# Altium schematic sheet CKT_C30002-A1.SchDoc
size 330 x 219 mm; PageSetup: Record=PageOptions|CenterHorizontal=True|CenterVertical=True|PrintScale=0.89|XCorrection=1.00|YCorrection=1.00|PrintKind=0|BorderSize=5000000|LeftOffset=0|BottomOffset=0|Orientation=2|PaperLength=1000|PaperWidth=1000|Scale=100|PaperSource=7|PrintQuality=-4|MediaType=1|DitherType=10|PaperKind=A4|PrintScaleMode=1
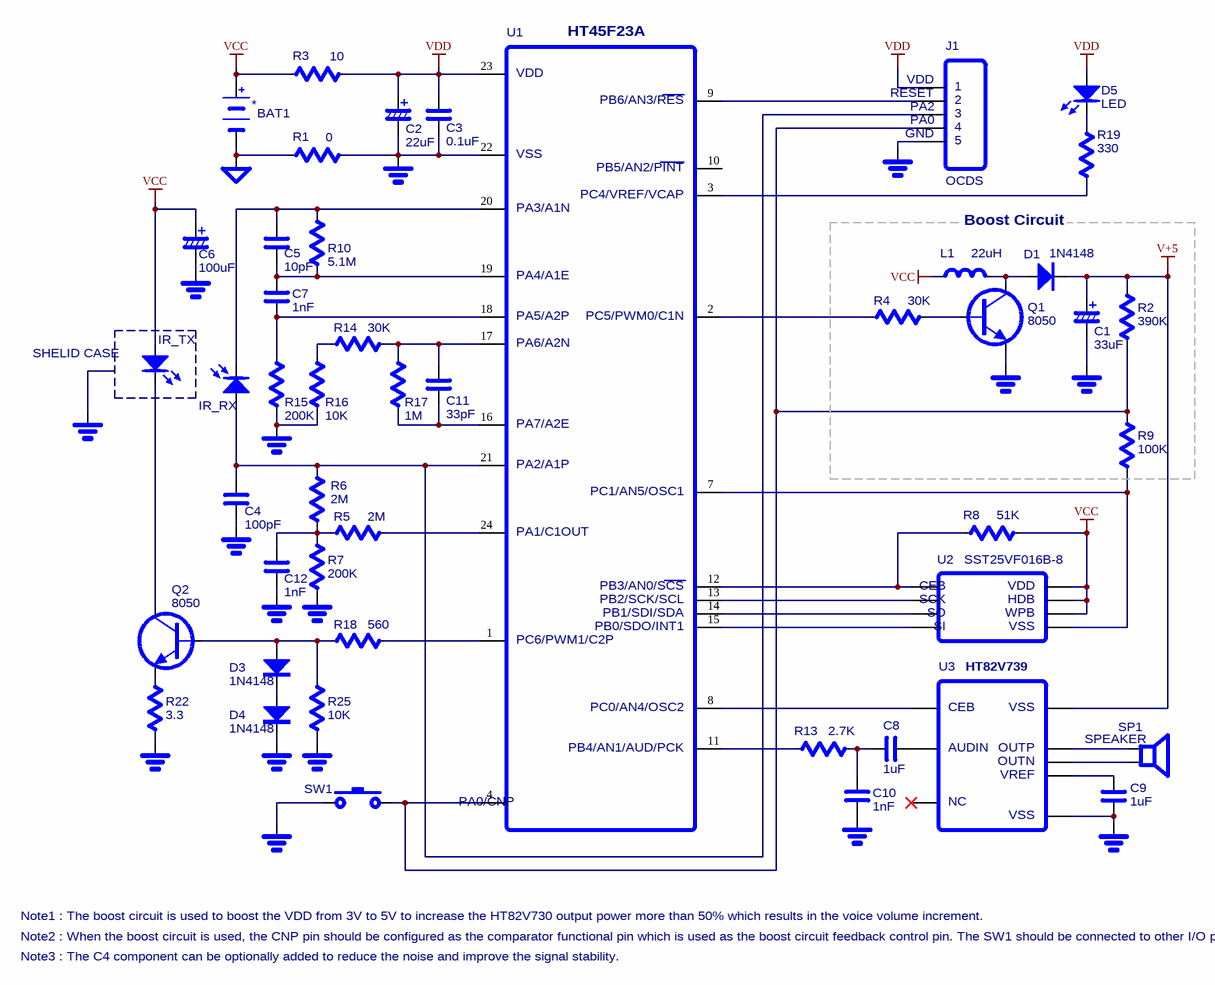
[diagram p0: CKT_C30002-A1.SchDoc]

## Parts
(Parts that share a designator on the sheet are numbered #1, #2 ... from top to bottom, then left to right.)
*18#1  GND(1)  (value not drawn)
*18#2  GND(1)  (value not drawn)
*18#3  GND(1)  (value not drawn)
*18#4  GND(1)  (value not drawn)
*18#5  GND(1)  (value not drawn)
*18#6  GND(1)  (value not drawn)
*18#7  GND(1)  (value not drawn)
*18#8  GND(1)  (value not drawn)
*18#9  GND(1)  (value not drawn)
*18#10  GND(1)  (value not drawn)
*18#11  GND(1)  (value not drawn)
*18#12  GND(1)  (value not drawn)
*18#13  GND(1)  (value not drawn)
*18#14  GND(1)  (value not drawn)
*18#15  GND(1)  (value not drawn)
*18#16  GND(1)  (value not drawn)
BAT1  *  [CR2032]
C1  33uF
C2  22uF
C3  0.1uF
C4  100pF
C5  10pF
C6  100uF
C7  1nF
C8  1uF
C9  1uF
C10  1nF
C11  33pF
C12  1nF
D1  1N4148  [SMC]
D3  1N4148  [SMC]
D4  1N4148  [SMC]
D5  LED  [LED3M]
D?  IR_RX  [LED3M]
f6  GND(2)  (value not drawn)
J1  OCDS
L1  22uH
LED?  IR_TX  [LED3M]
Q1  8050  [TO-226-AA]
Q2  8050  [TO-226-AA]
R1  0
R2  390K
R3  10
R4  30K
R5  2M
R6  2M
R7  200K
R8  51K
R9  100K
R10  5.1M
R13  2.7K
R14  30K
R15  200K
R16  10K
R17  1M
R18  560
R19  330
R22  3.3
R25  10K
SP1  SPEAKER  [PIN2]
SW1  SW(2)  (value not drawn)
U1  HT45F23A  [HT45F23A_24SSOP]
U2  SST25VF016B-8  [H8]
U3  HT82V739

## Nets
V+5: C1.1 D1.2(K) R2.2 U3.8(VDD)
VCC: BAT1.1(+) C6.1 L1.1 LED?.1(A) R3.1 R8.1 U2.3(WPB) U2.7(HDB) U2.8(VDD)
VDD: C2.1 C3.2 D5.1(A) J1.1(VDD) R3.2 U1.23(VDD)
Net*18#1_?1: *18#1.?1 J1.5(GND)
Net*18#2_?1: *18#2.?1 C2.2 C3.1 R1.2 U1.22(VSS)
Net*18#3_?1: *18#3.?1 C6.2
Net*18#4_?1: *18#4.?1 Q1.3(E)
Net*18#5_?1: *18#5.?1 C1.2
Net*18#7_?1: *18#7.?1 R15.1 R16.1
Net*18#8_?1: *18#8.?1 C4.2
Net*18#9_?1: *18#9.?1 C12.1
Net*18#10_?1: *18#10.?1 R7.1
Net*18#11_?1: *18#11.?1 R22.1
Net*18#12_?1: *18#12.?1 D4.2(K)
Net*18#13_?1: *18#13.?1 R25.1
Net*18#14_?1: *18#14.?1 C10.2
Net*18#15_?1: *18#15.?1 SW1.1
Net*18#16_?1: *18#16.?1 C9.1 U3.4(VSS)
NetBAT1_2: BAT1.2(-) f6.?1 R1.1
NetC4_1: C4.1 D?.1(A) J1.3(PA2) R6.2 U1.21(PA2/A1P)
NetC5_1: C5.1 C7.2 R10.1 U1.19(PA4/A1E)
NetC5_2: C5.2 D?.2(K) R10.2 U1.20(PA3/A1N)
NetC7_1: C7.1 R15.2 U1.18(PA5/A2P)
NetC8_1: C8.1 U3.2(AUDIN)
NetC8_2: C8.2 C10.1 R13.1
NetC9_2: C9.2 U3.3(VREF)
NetC11_1: C11.1 R17.1 U1.16(PA7/A2E)
NetC11_2: C11.2 R14.2 R17.2 U1.17(PA6/A2N)
NetC12_2: C12.2 R5.1 R6.1 R7.2
NetD1_1: D1.1(A) L1.2 Q1.1(C)
NetD3_1: D3.1(A) Q2.2(B) R18.1 R25.2
NetD3_2: D3.2(K) D4.1(A)
NetD5_2: D5.2(K) R19.2
NetJ1_2: J1.2(OCDSCK) U1.9(PB6/AN3/~{RE}S)
NetJ1_4: J1.4(PA0) R2.1 R9.2 SW1.2 U1.4(PA0/CNP)
NetLED?_2: LED?.2(K) Q2.1(C)
NetQ1_2: Q1.2(B) R4.2
NetQ2_3: Q2.3(E) R22.2
NetR4_1: R4.1 U1.2(PC5/PWM0/C1N)
NetR5_2: R5.2 U1.24(PA1/C1OUT)
NetR8_2: R8.2 U1.12(PB3/AN0/~{SCS}) U2.8(CEB)
NetR9_1: R9.1 U1.7(PC1/AN5/OSC1) U2.4(VSS)
NetR13_2: R13.2 U1.11(PB4/AN1/AUD/PCK)
NetR14_1: R14.1 R16.2
NetR18_2: R18.2 U1.1(PC6/PWM1/C2P)
NetR19_1: R19.1 U1.3(PC4/VREF/VCAP)
NetSP1_1: SP1.1 U3.7(OUTP)
NetSP1_2: SP1.2 U3.1(OUTN)
NetU1_8: U1.8(PC0/AN4/OSC2) U3.5(CEB)
NetU1_13: U1.13(PB2/SCK/SCL) U2.6(SCK)
NetU1_14: U1.14(PB1/SDI/SDA) U2.2(SO)
NetU1_15: U1.15(PB0/SDO/INT1) U2.5(SI)

Not connected (* = marked no-connect by the designer): *18#6 ?1; U1 10(PB5/AN2/~{PINT}); U3 6(NC)*

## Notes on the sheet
- Boost Circuit
- SHELID CASE
- Note1 : The boost circuit is used to boost the VDD from 3V to 5V to increase the HT82V730 output power more than 50% which results in the voice volume increment.
- Note2 : When the boost circuit is used, the CNP pin should be configured as the comparator functional pin which is used as the boost circuit feedback control pin. The SW1 should be connected to other I/O pin rather than PA0.
- Note3 : The C4 component can be optionally added to reduce the noise and improve the signal stability.

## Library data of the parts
*18#1-*18#16 = GND(1): GND
BAT1 = Battery(2): Battery
C1 C2 C6 = Cap(2): Capacitor
C3-C5 C7-C12 = Cap(1): Capacitor
D1 D3 D4 = Diode(1): Diode
D5 LED? = LED(1): Typical INFRARED GaAs LED
D? = Photo Diode(1): Photo Diode
f6 = GND(2): GND
L1 = Inductor (1)_2: Inductor; Code_IEC: 1005
Q1 Q2 = NPN(2): NPN Bipolar Transistor
R1-R10 R13-R19 R22 R25 = Resistor(1)_1: Resisitor
SP1 = Speaker(1): Loudspeaker
SW1 = SW(2): Switch
U2 = SPI_Flash: 砏��: PITCH 2.54mm 8pin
